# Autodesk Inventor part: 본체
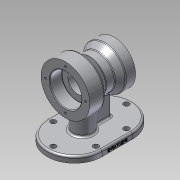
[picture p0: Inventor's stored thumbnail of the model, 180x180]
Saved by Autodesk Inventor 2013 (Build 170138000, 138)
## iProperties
Created: 2020-01
Part Number: 본체
Material: 알루미늄 6061
Document SubType Name: Modeling
Designer: Administrator
Density: 2.71 g/cm^3
Mass: 924.16 g
Surface Area: 656.156 cm^2
Volume: 341.018 cm^3
Author: Administrator
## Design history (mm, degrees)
sketch "스케치1"
  geometry: L1 (-40, 0)-(40, 0); L2 (-40, 0)-(-40, 26); L3 (-40, 40)-(-16, 40); L4 (13.289, 27.5)-(24, 35); L5 (40, 35)-(40, 20); L6 (-20, 26)-(-20, 16); L7 (-20, 16)-(23, 16); L8 (23, 16)-(23, 20); L9 (23, 20)-(40, 20); L10 (-20, 26)-(-40, 26); L11 (-40, 26)-(-40, 40); L12 (40, 20)-(40, 0); L13 (13.289, 27.5)-(-1.103, 27.5); L14 (-1.103, 27.5)-(-16, 40); L15 (40, 35)-(24, 35); 1 further point
  constraints: 30 end point, 9 parallel, 7 perpendicular, 2 midpoint, 1 horizontal
  dimensions: "d0" = 80 distance of L1.start L1.end; "d12" = 52 diameter of L10 L1; "d13" = 32 diameter of L7 L1; "d14" = 40 diameter of L9 L1; "d15" = 20 distance of L6.start L2.end; "d16" = 17 distance of L8.end L5.end; "d83" = 35 deg angle of L4 L13; "d84" = 40 deg angle of L13 L14; "d85" = 55 diameter of L13 L1; "d86" = 24 distance of L3.start L3.end; "d87" = 80 diameter of L3.start L1; "d88" = 16 distance of L5.start L4.end; "d89" = 70 diameter of L15 L1
revolve "회전1" sketch "스케치1" stored, may be unused: angle "d17" = 90 deg
sketch "스케치2"
  geometry: L1 (-70, -70)-(70, -70); L2 (70, -70)-(70, -80); L3 (70, -80)-(-70, -80); L4 (-70, -80)-(-70, -70); L5 (-40, -40)-(-40, 40) reference; 1 further point
  constraints: 8 end point, 2 parallel, 1 horizontal, 1 perpendicular
  dimensions: "d18" = 10 distance of L1.end L2.end; "d20" = 140 distance of L2.end L3.end; "d21" = 30 distance between parallel lines of L4 L5; "d22" = 80 distance from line of point (0, 0) L3
extrude "돌출1" join sketch "스케치2" stored distance "d23" = 90; taper "d24" = 0 deg
sketch "스케치3"
  geometry: L1 (0, 90)-(0, 0) reference; C1 r 16 at (58, 45); 2 further points
  constraints: 1 centre point, 1 horizontal alignment, 1 midpoint
  dimensions: "d25" = 32 diameter of C1; "d27" = 58 distance from line of C1.centre L1
extrude "돌출2" join sketch "스케치3" stored distance "d28" = 0; taper "d29" = 0 deg
sketch "스케치9"
  geometry: L1 (30, -70)-(30, -39.869); L2 (24, -35)-(40, -35) reference; L3 (-70, -70)-(70, -70) reference; L4 (40, -35)-(40, 35) reference; 1 further point
  constraints: 2 end point, 1 point on line, 1 vertical
  dimensions: "d90" = 10 distance between parallel lines of L4 L1
feature "리브2" sketch "스케치9" dims "d91" = 1, "d92" = 10, "d93" = 0, "d94" = 0, "d95" = 1, "d96" = 1
fillet "모깎기1" dims "d37" = 45
sketch "스케치5"
  geometry: C1 r 26 at (0, 0) reference; 1 further point
  constraints: 1 vertical alignment
  dimensions: "d38" = 33 distance of C1.centre point (0, 33)
hole "구멍1" sketch "스케치5" at (0, 33) diameter "d39" = 3.242; stored, may be unused: countersink angle "d43" = 90 deg, drill point angle "d45" = 118 deg; dims "d40" = 9, "d41" = 4, "d42" = 2, "d44" = 11
sketch "스케치6"
  geometry: C1 r 20 at (0, 0) reference; 1 further point
  constraints: 1 vertical alignment
  dimensions: "d49" = 27.5 distance of C1.centre point (0, 27.5)
hole "구멍2" sketch "스케치6" at (0, 27.5) diameter "d50" = 3.242; stored, may be unused: countersink angle "d54" = 90 deg, drill point angle "d56" = 118 deg; dims "d51" = 9, "d52" = 4, "d53" = 2, "d55" = 11
sketch "스케치7"
  geometry: L1 (50, 0)-(0, 0) reference; L2 (0, 90)-(50, 90) reference; L3 (50, 10)-(0, 10); L4 (0, 80)-(50, 80); A1 r 45 centre (0, 45) between (0, 90) and (0, 0) reference; A2 r 45 centre (50, 45) between (50, 0) and (50, 90) reference; A3 r 35 centre (50, 45) between (50, 10) and (50, 80); A4 r 35 centre (0, 45) between (0, 80) and (0, 10); 7 further points
  constraints: 6 point on circle, 4 coincident, 4 end point, 2 centre point, 3 other
  dimensions: "d60" = 35 radius of A3
hole "구멍3" sketch "스케치7" at (0, 80), (50, 80), (50, 10), (0, 10), (-35, 45), (85, 45) diameter "d62" = 9; stored, may be unused: countersink angle "d66" = 90 deg, drill point angle "d68" = 0 deg; dims "d63" = 9, "d64" = 4, "d65" = 2, "d67" = 11
sketch "스케치8"
  geometry: L1 (-70, -70)-(-70, -80) reference; L2 (70, -80)-(25, -80) reference; 2 further points
  constraints: 1 other
  dimensions: "d69" = 70 distance from line of point (0, -76) L1; "d70" = 4 distance from line of L2 point (0, -76)
feature "엠보싱1" sketch "스케치8" dims "d71" = 0.5, "d72" = 0
chamfer "모따기1" distance "d73" = 1; stored, may be unused: second distance "d74" = 2, angle "d75" = 45 deg
fillet "모깎기2" dims "d76" = 0.3
fillet "모깎기3" dims "d77" = 3
fillet "모깎기10" dims "d99" = 3
fillet "모깎기11" dims "d100" = 3
fillet "모깎기12" dims "d101" = 3
node "솔리드1"
pattern_circular "원형 패턴1" dims angle "d47" = 360 deg
pattern_circular "원형 패턴2" dims angle "d58" = 360 deg
